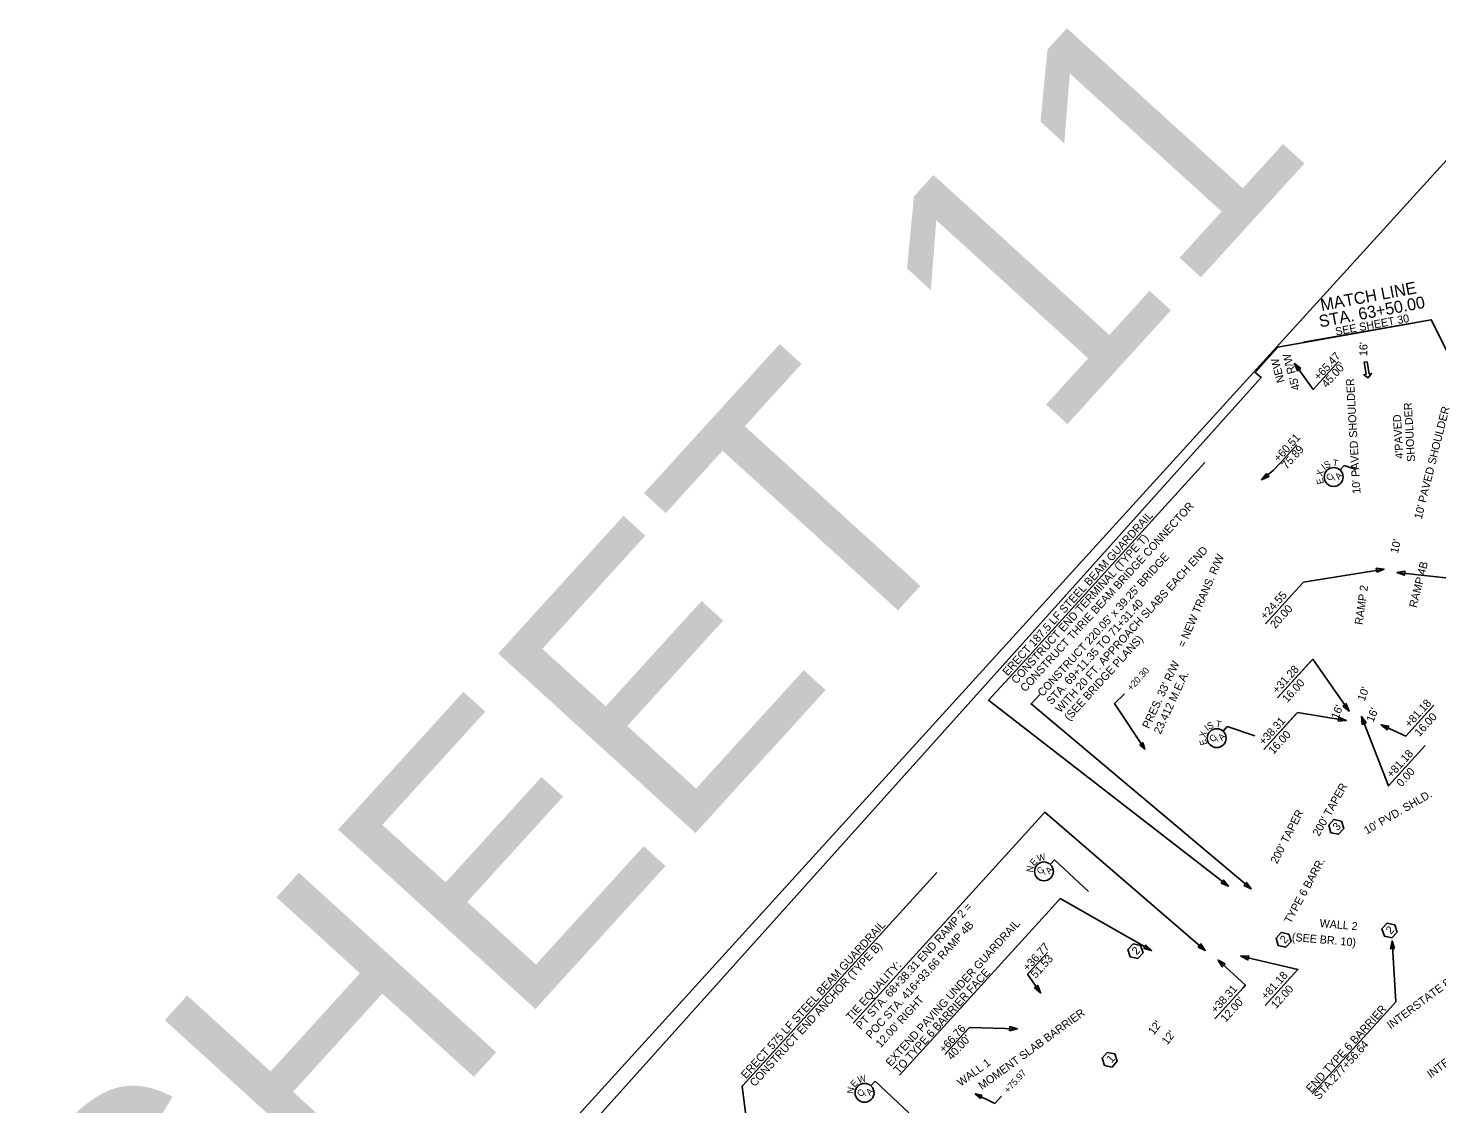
# Model space of a CAD drawing. Extents: x 1608705 to 1610581, y 1091647 to 1093887.
# Drawn here: x 1608705 to 1609761, y 1093080 to 1093887 of the extents above; entities that cross this region are included whole.
import ezdxf

# ---------------------------------------------------------------- set-up
doc = ezdxf.new("R2010")
doc.units = 0
for name, color, linetype in [('Level 14', 7, 'Continuous'), ('Level 2', 7, 'Continuous'), ('Plan_Clip', 7, 'Continuous'), ('RD_EX_Control_Access', 7, 'Continuous'), ('RD_EX_RW_TX', 7, 'Continuous'), ('RD_PD_GR_TX', 7, 'Continuous'), ('RD_PD_RW_TX', 7, 'Continuous'), ('RD_SHT_MatchLine', 7, 'Continuous'), ('RD_SHT_Misc1', 7, 'Continuous'), ('RD_SHT_TX', 7, 'Continuous'), ('RD_TX_Bridge', 7, 'Continuous'), ('RD_TX_RoadID', 7, 'Continuous'), ('RD_TX_RW', 7, 'Continuous')]:
    doc.layers.add(name, color=color, linetype=linetype)

msp = doc.modelspace()

# ---------------------------------------------------------------- linework, layer by layer
at = {"layer": 'Level 14'}
msp.add_lwpolyline([(1609708.7, 1093636.8), (1609706.4, 1093636.4), (1609707.8, 1093627.4), (1609706.2, 1093627.1), (1609709.4, 1093624.8), (1609711.8, 1093628), (1609710.2, 1093627.7)], close=True, dxfattribs=at)
at = {"layer": 'Level 2'}
for p, q in [((1609655.8, 1093574.6), (1609643.1, 1093560.6)), ((1609468.9, 1093194), (1609454.9, 1093178.7))]:
    msp.add_line(p, q, dxfattribs=at)
for points in [[(1608729.1, 1092645.4), (1609856.1, 1093884.6), (1610563.7, 1093241), (1609436.7, 1092001.8)], [(1609633.1, 1093553.1), (1609629.5, 1093548.3), (1609635, 1093550.7)], [(1609459.2, 1093167.4), (1609463.8, 1093163.6), (1609461.7, 1093169.2)]]:
    msp.add_lwpolyline(points, close=True, dxfattribs=at)
for points in [[(1609643.1, 1093560.6), (1609638.2, 1093555.2), (1609629.5, 1093548.3)], [(1609454.9, 1093178.7), (1609454, 1093177.6), (1609463.8, 1093163.6)]]:
    msp.add_lwpolyline(points, dxfattribs=at)
at = {"layer": 'Plan_Clip'}
msp.add_lwpolyline([(1609149.6, 1092364.4), (1609090, 1092453.4), (1608942, 1092657.6), (1608947.4, 1092661.1), (1608865.5, 1092773.4), (1609629.1, 1093625.1), (1609624.6, 1093628.8), (1609641.7, 1093647.8), (1609756.7, 1093668.3), (1609768.8, 1093644), (1609859.4, 1093621.4), (1610115.1, 1093602.3), (1610196.6, 1093489.1), (1610193.3, 1093486.6), (1610273.8, 1093378.2), (1610243.5, 1093357.4), (1610329.6, 1093201), (1610402.7, 1093068.4), (1609510.9, 1092089.3)], dxfattribs=at)
msp.add_lwpolyline([(1609149.6, 1092364.4), (1609090, 1092453.4), (1608942, 1092657.6), (1608947.4, 1092661.1), (1608865.5, 1092773.4), (1609629.1, 1093625.1), (1609624.6, 1093628.8), (1609641.7, 1093647.8), (1609756.7, 1093668.3), (1609768.8, 1093644), (1609859.4, 1093621.4), (1610115.1, 1093602.3), (1610196.6, 1093489.1), (1610193.3, 1093486.6), (1610273.8, 1093378.2), (1610243.5, 1093357.4), (1610329.6, 1093201), (1610402.7, 1093068.4), (1609510.9, 1092089.3)], dxfattribs=at)
at = {"layer": 'RD_EX_Control_Access'}
for p, q in [((1609688.2, 1093555.6), (1609691.3, 1093559)), ((1609691.3, 1093559), (1609700.5, 1093556)), ((1609600.6, 1093359.8), (1609603.6, 1093363.2)), ((1609603.6, 1093363.2), (1609624.4, 1093356.4)), ((1609471.1, 1093260), (1609474.2, 1093263.4)), ((1609474.2, 1093263.4), (1609499.6, 1093239.7)), ((1609336.6, 1093093.9), (1609339.7, 1093097.3)), ((1609339.7, 1093097.3), (1609365.1, 1093073.6))]:
    msp.add_line(p, q, dxfattribs=at)
for centre in [(1609683.5, 1093550.4), (1609595.8, 1093354.6), (1609466.3, 1093254.7), (1609331.8, 1093088.7)]:
    msp.add_circle(centre, 7.08, dxfattribs=at)
at = {"layer": 'RD_EX_RW_TX'}
for points in [[(1609526.6, 1093387.7), (1609519.2, 1093380.5), (1609542, 1093346.4)], [(1609434.4, 1093086.1), (1609429.4, 1093080.7), (1609414.8, 1093087.8)]]:
    msp.add_lwpolyline(points, dxfattribs=at)
for points in [[(1609538.2, 1093349.7), (1609542, 1093346.4), (1609540.4, 1093351.2)], [(1609419.7, 1093086.9), (1609414.8, 1093087.8), (1609418.6, 1093084.5)]]:
    msp.add_lwpolyline(points, close=True, dxfattribs=at)
at = {"layer": 'RD_PD_GR_TX'}
for p, q in [((1609586.8, 1093561.2), (1609440.1, 1093399.9)), ((1609385.9, 1093253.8), (1609240.6, 1093094.1))]:
    msp.add_line(p, q, dxfattribs=at)
for points in [[(1609440.1, 1093399.9), (1609424.8, 1093383), (1609604.6, 1093243.5)], [(1609240.6, 1093094.1), (1609240, 1093093.4), (1609260.4, 1092933.5)]]:
    msp.add_lwpolyline(points, dxfattribs=at)
msp.add_lwpolyline([(1609599.1, 1093245.8), (1609604.6, 1093243.5), (1609601, 1093248.2)], close=True, dxfattribs=at)
at = {"layer": 'RD_SHT_MatchLine'}
msp.add_line((1609661, 1093651.4), (1609756.7, 1093668.3), dxfattribs=at)
at = {"layer": 'RD_SHT_TX'}
for p, q in [((1609657.5, 1093467.8), (1609632.4, 1093440.3)), ((1609666.5, 1093412.3), (1609641.4, 1093384.7)), ((1609758.7, 1093379.2), (1609739.7, 1093358.3)), ((1609655.2, 1093372.5), (1609631.2, 1093346)), ((1609752.2, 1093349), (1609727.1, 1093321.5)), ((1609442.7, 1093272.4), (1609323.2, 1093140.9)), ((1609472.6, 1093227.9), (1609358.1, 1093101.9)), ((1609651.1, 1093175.1), (1609632.1, 1093154.2)), ((1609615.6, 1093167.5), (1609594.4, 1093144.1)), ((1609726.2, 1093152.5), (1609667.4, 1093087.8))]:
    msp.add_line(p, q, dxfattribs=at)
for points in [[(1609657.5, 1093467.8), (1609660.9, 1093471.6), (1609721.3, 1093481.4)], [(1609800.5, 1093477.8), (1609795.1, 1093471.9), (1609730.9, 1093478.9)], [(1609641.4, 1093384.7), (1609667.8, 1093413.7), (1609695.1, 1093374.8)], [(1609631.2, 1093346), (1609656.4, 1093373.8), (1609692.9, 1093367.9)], [(1609758.7, 1093379.2), (1609737.7, 1093356.1), (1609719, 1093364.6)], [(1609752.2, 1093349), (1609724.7, 1093318.8), (1609704.3, 1093370.9)], [(1609442.7, 1093272.4), (1609466.9, 1093299), (1609587.2, 1093195.4)], [(1609472.6, 1093227.9), (1609478.5, 1093234.3), (1609547, 1093195.3)], [(1609726.2, 1093152.5), (1609730.1, 1093156.8), (1609727.3, 1093202.6)], [(1609615.6, 1093167.5), (1609617.3, 1093169.3), (1609596.8, 1093188.2)], [(1609651.1, 1093175.1), (1609656.7, 1093181.2), (1609613.9, 1093191.2)]]:
    msp.add_lwpolyline(points, dxfattribs=at)
for points in [[(1609715.8, 1093479), (1609721.3, 1093481.4), (1609715.3, 1093482)], [(1609736.9, 1093479.8), (1609730.9, 1093478.9), (1609736.5, 1093476.7)], [(1609690.5, 1093378.6), (1609695.1, 1093374.8), (1609693, 1093380.4)], [(1609687, 1093367.3), (1609692.9, 1093367.9), (1609687.5, 1093370.3)], [(1609707.8, 1093366), (1609704.3, 1093370.9), (1609705, 1093364.9)], [(1609724.9, 1093363.6), (1609719, 1093364.6), (1609723.6, 1093360.8)], [(1609689.4, 1093292.3), (1609683.7, 1093293.6), (1609679.8, 1093289.3), (1609681.5, 1093283.7), (1609687.2, 1093282.5), (1609691.1, 1093286.8)], [(1609729.3, 1093214.7), (1609723.6, 1093215.9), (1609719.7, 1093211.6), (1609721.5, 1093206.1), (1609727.2, 1093204.8), (1609731.1, 1093209.1)], [(1609649.9, 1093207.7), (1609644.2, 1093208.9), (1609640.3, 1093204.6), (1609642, 1093199.1), (1609647.7, 1093197.9), (1609651.6, 1093202.2)], [(1609538.8, 1093199.2), (1609533.1, 1093200.5), (1609529.2, 1093196.2), (1609531, 1093190.7), (1609536.7, 1093189.4), (1609540.6, 1093193.7)], [(1609541.2, 1093196.8), (1609547, 1093195.3), (1609542.7, 1093199.5)], [(1609581.8, 1093198), (1609587.2, 1093195.4), (1609583.8, 1093200.3)], [(1609729.2, 1093196.9), (1609727.3, 1093202.6), (1609726.1, 1093196.7)], [(1609602.1, 1093185.4), (1609596.8, 1093188.2), (1609600, 1093183.1)], [(1609619.9, 1093191.4), (1609613.9, 1093191.2), (1609619.2, 1093188.3)], [(1609519.5, 1093117.8), (1609513.8, 1093119), (1609509.9, 1093114.7), (1609511.7, 1093109.2), (1609517.4, 1093108), (1609521.3, 1093112.3)]]:
    msp.add_lwpolyline(points, close=True, dxfattribs=at)
at = {"layer": 'RD_TX_Bridge'}
msp.add_lwpolyline([(1609463.1, 1093387.3), (1609456.7, 1093380.2), (1609621.6, 1093241.5)], dxfattribs=at)
msp.add_lwpolyline([(1609616.1, 1093244), (1609621.6, 1093241.5), (1609618.1, 1093246.4)], close=True, dxfattribs=at)
at = {"layer": 'RD_TX_RW'}
for p, q in [((1609687.2, 1093637.1), (1609673.1, 1093621.6)), ((1609406, 1093132.8), (1609392.1, 1093117.5))]:
    msp.add_line(p, q, dxfattribs=at)
for points in [[(1609673.1, 1093621.6), (1609668.1, 1093616.1), (1609654.2, 1093635.6)], [(1609406, 1093132.8), (1609410.4, 1093137.6), (1609446.3, 1093136.6)]]:
    msp.add_lwpolyline(points, dxfattribs=at)
for points in [[(1609658.9, 1093631.8), (1609654.2, 1093635.6), (1609656.3, 1093630)], [(1609440.5, 1093135.2), (1609446.3, 1093136.6), (1609440.6, 1093138.3)]]:
    msp.add_lwpolyline(points, close=True, dxfattribs=at)

# ---------------------------------------------------------------- texts
at = {"layer": 'RD_EX_Control_Access'}
for s, rotation, p in [('T', 350.7639, (1609682.4, 1093558.7)), ('X', 72.8073, (1609675, 1093550.5)), ('I', 37.6458, (1609676.7, 1093555.3)), ('S', 25.9253, (1609677.8, 1093556.6)), ('C', 47.7105, (1609680.8, 1093546.9)), ('A', 47.7105, (1609687.5, 1093547.9)), ('E', 106.2944, (1609676.4, 1093545.8)), ('/', 47.7105, (1609684.4, 1093547.7)), ('I', 37.6458, (1609589, 1093359.6)), ('S', 25.9253, (1609590.1, 1093360.8)), ('T', 350.7639, (1609594.8, 1093363)), ('X', 72.8073, (1609587.4, 1093354.7)), ('E', 106.2944, (1609588.7, 1093350.1)), ('C', 47.7105, (1609593.2, 1093351.1)), ('/', 47.7105, (1609596.7, 1093351.9)), ('A', 47.7105, (1609599.9, 1093352.2)), ('W', 15.3223, (1609461.9, 1093261.9)), ('N', 80.6222, (1609458, 1093253.7)), ('E', 47.1351, (1609458.8, 1093258.5)), ('C', 47.7105, (1609463.9, 1093252)), ('/', 47.7105, (1609467.2, 1093252)), ('A', 47.7105, (1609470.4, 1093252.3)), ('E', 47.1351, (1609324.3, 1093092.4)), ('W', 15.3223, (1609327.4, 1093095.8)), ('N', 80.6222, (1609323.5, 1093087.7)), ('C', 47.7105, (1609329.2, 1093085.2)), ('/', 47.7105, (1609332.7, 1093086)), ('A', 47.7105, (1609335.9, 1093086.2))]:
    msp.add_text(s, height=5, rotation=rotation, dxfattribs=at).set_placement(p)
at = {"layer": 'RD_EX_RW_TX'}
for s, height, rotation, p in [('+20.30', 5, 47.7138, (1609531.8, 1093389.7)), ("PRES. 33' R/W", 6, 65.0474, (1609545.1, 1093361.2)), ('23.412 M.E.A.', 6, 65.0474, (1609553.7, 1093357.1)), ('+75.97', 5, 47.7138, (1609439.6, 1093088.1))]:
    msp.add_text(s, height=height, rotation=rotation, dxfattribs=at).set_placement(p)
at = {"layer": 'RD_PD_GR_TX'}
for s, rotation, p in [('ERECT 187.5 LF STEEL BEAM GUARDRAIL', 47.7154, (1609439, 1093400.9)), ('CONSTRUCT THRIE BEAM BRIDGE CONNECTOR', 47.7154, (1609452.3, 1093388.8)), ('CONSTRUCT END TERMINAL (TYPE T)', 47.7154, (1609445.6, 1093394.8)), ('ERECT 575 LF STEEL BEAM GUARDRAIL', 47.7138, (1609242.9, 1093098.8)), ('CONSTRUCT END ANCHOR (TYPE B)', 47.7138, (1609249.5, 1093092.8))]:
    msp.add_text(s, height=6, rotation=rotation, dxfattribs=at).set_placement(p)
at = {"layer": 'RD_PD_RW_TX'}
for s, rotation, p in [('NEW', 105.048, (1609646.9, 1093621.9)), ("45' R/W", 105.048, (1609658.3, 1093616.2)), ('= NEW TRANS. R/W', 66.568, (1609571.7, 1093422))]:
    msp.add_text(s, height=6, rotation=rotation, dxfattribs=at).set_placement(p)
at = {"layer": 'RD_SHT_MatchLine'}
for s, height, rotation, p in [('MATCH LINE', 9, 10.5641, (1609674.5, 1093674.8)), ('STA. 63+50.00', 9, 10.5641, (1609673.3, 1093662.5)), ('SEE SHEET 30', 6, 10.5407, (1609685.3, 1093656.4))]:
    msp.add_text(s, height=height, rotation=rotation, dxfattribs=at).set_placement(p)
at = {"layer": 'RD_SHT_Misc1'}
msp.add_text('SHEET 11', height=200, rotation=47.7138, dxfattribs=at).set_placement((1608820.3, 1092860.4))
at = {"layer": 'RD_SHT_TX'}
for s, rotation, p in [("16'", 88.8686, (1609708.7, 1093641)), ("10' PAVED SHOULDER", 93.3127, (1609703.7, 1093538)), ('SHOULDER', 93.3127, (1609744.6, 1093561.9)), ("4'PAVED", 93.3127, (1609735.8, 1093564.3)), ("10' PAVED SHOULDER", 75.9613, (1609749.5, 1093518.4)), ("10'", 76.5181, (1609731.6, 1093492.7)), ('+24.55', 47.7138, (1609632.3, 1093443.1)), ('20.00', 47.7138, (1609639.7, 1093436.4)), ('+31.28', 47.7138, (1609641.3, 1093387.5)), ('16.00', 47.7138, (1609648.7, 1093380.8)), ("10'", 70.2352, (1609706.7, 1093381.9)), ("16'", 67.8513, (1609686.8, 1093368.3)), ("16'", 67.8513, (1609713.2, 1093366.1)), ('+81.18', 47.7138, (1609740.5, 1093362.1)), ('16.00', 47.7138, (1609747.9, 1093355.4)), ('+38.31', 47.7138, (1609631.1, 1093348.8)), ('16.00', 47.7138, (1609638.4, 1093342.1)), ('+81.18', 47.7138, (1609727, 1093324.3)), ('0.00', 47.7138, (1609734.4, 1093317.6)), ("200' TAPER", 60.6649, (1609672.5, 1093280.5)), ("10' PVD. SHLD.", 30.2008, (1609708.4, 1093282.2)), ("200' TAPER", 62.9281, (1609641.1, 1093259.9)), ('3', 47.7138, (1609686.5, 1093284.7)), ('TYPE 6 BARR.', 61.5266, (1609651.3, 1093215.1)), ('PT STA. 68+38.31 END RAMP 2 =', 47.7138, (1609329.1, 1093135.6)), ('POC STA. 416+93.66 RAMP 4B', 47.7138, (1609336.5, 1093128.8)), ('EXTEND PAVING UNDER GUARDRAIL', 47.7138, (1609351.4, 1093108)), ('WALL 2', 355.0778, (1609672.8, 1093213)), ('2', 47.7138, (1609647, 1093200.1)), ('(SEE BR. 10)', 355.0778, (1609652, 1093202.6)), ('2', 47.7138, (1609726.4, 1093207.1)), ('2', 47.7138, (1609535.9, 1093191.6)), ('TIE EQUALITY:', 47.7138, (1609321.7, 1093142.3)), ('TO TYPE 6 BARRIER FACE', 47.7138, (1609357.4, 1093102.6)), ('+81.18', 47.7138, (1609632.9, 1093158)), ("12.00' RIGHT", 47.7138, (1609343.9, 1093122.1)), ('+38.31', 47.7138, (1609595.1, 1093147.9)), ('12.00', 47.7138, (1609640.3, 1093151.3)), ("12.00'", 47.7138, (1609602.5, 1093141.2)), ('END TYPE 6 BARRIER', 47.7138, (1609666.6, 1093088.5)), ('MOMENT SLAB BARRIER', 36.0872, (1609419.8, 1093090.7)), ("12'", 52.574, (1609548.6, 1093131.6)), ("12'", 52.574, (1609558.8, 1093124.2)), ('STA.277+56.64', 47.7138, (1609672.5, 1093083.1)), ('WALL 1', 36.156, (1609403.9, 1093093.2)), ('1', 47.7138, (1609517, 1093110.6))]:
    msp.add_text(s, height=6, rotation=rotation, dxfattribs=at).set_placement(p)
at = {"layer": 'RD_TX_Bridge'}
for s, p in [("CONSTRUCT 220.05' x 39.25' BRIDGE", (1609465.3, 1093385.3)), ('WITH 20 FT. APPROACH SLABS EACH END', (1609478.6, 1093373.1)), ('STA. 69+11.35 TO 71+31.40', (1609471.9, 1093379.2)), ('(SEE BRIDGE PLANS)', (1609485.3, 1093367.1))]:
    msp.add_text(s, height=6, rotation=47.7138, dxfattribs=at).set_placement(p)
at = {"layer": 'RD_TX_RoadID'}
for s, rotation, p in [('RAMP 4B', 75.9491, (1609745.7, 1093452)), ('RAMP 2', 81.7575, (1609705.1, 1093439.3)), ('INTERSTATE 85 SB', 36.62, (1609726.2, 1093136.2)), ('INTERSTATE 85 NB', 36.62, (1609756.3, 1093099.4))]:
    msp.add_text(s, height=6, rotation=rotation, dxfattribs=at).set_placement(p)
at = {"layer": 'RD_TX_RW'}
for s, p in [('+65.47', (1609672.4, 1093622.3)), ("45.00'", (1609678.3, 1093616.9)), ('+60.51', (1609642.3, 1093561.2)), ('75.89', (1609648.2, 1093555.9)), ('+36.77', (1609454.2, 1093179.4)), ('51.53', (1609460.1, 1093174)), ('+66.76', (1609391.4, 1093118.2)), ("40.00'", (1609397.3, 1093112.8))]:
    msp.add_text(s, height=6, rotation=47.7138, dxfattribs=at).set_placement(p)

doc.saveas('drawing.dxf')
